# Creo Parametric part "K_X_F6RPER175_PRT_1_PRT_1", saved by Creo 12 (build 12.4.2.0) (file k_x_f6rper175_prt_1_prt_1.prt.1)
Units: Custom; MM, KILOGRAM, SECS

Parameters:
  PTC_WM_ITERATION = "0"
  PTC_WM_VERSION = "-.0"
  PTC_WM_LIFECYCLE_STATE = "In Work"
  PTC_WM_LIFECYCLE = "MO_CADDocument"
  PTC_WM_CREATED_BY = "Maximilian Roepper (Z0017RMS: MO)"
  PTC_WM_CREATED_ON = "18-Sep-26 11:36:42 AM"
  PTC_WM_MODIFIED_BY = "Maximilian Roepper (Z0017RMS: MO)"
  PTC_WM_MODIFIED_ON = "18-Sep-26 11:36:46 AM"
  PDMLINKNUMBER = "PDM000071454783"
  PTC_WM_NAME = "k_x_f6rper175_prt_1_prt_1.prt"
  PTC_WM_NUMBER = "PDM000071454783"

Other parameters: WEIGHT, WEIGHT_FACTOR, WEIGHT_ADD, _MASS_TEMP, _DIFF_TEMP, MC_ERRORS, SUPPLIER

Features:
  1. coordinate system
  2. datum plane "PRT_YZ"
  3. datum plane "PRT_XY"
  4. datum plane "PRT_XZ"
  5. coordinate system
  6. datum axis
  7. datum axis
  8. datum axis
  9. coordinate system
  10. imported feature
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
Other named items: PRT, SIEMENS_MO, DRW_VIEW_ORG, PRT_X, PRT_Y, PRT_Z, CS0, ROUGH_GROB

Layers: 00_STD_CSYS-KSYS, 01_STD_PLANES-EBENEN, 02_STD_AXES-ACHSEN, 03_STD_CSYS-KSYS, 24_IMPORT_FEAT-IMPORT_KE

Surfaces: 10 plane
